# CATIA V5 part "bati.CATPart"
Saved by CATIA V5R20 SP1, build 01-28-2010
Part number: bati
Bounding box of the stored display mesh (mm): x -46.352 to 253.648, y 0 to 1170, z -91.16 to 708.84
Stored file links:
  C:\Users\Manon\Desktop\IAO\Pieces\bati.CATPart
  C:\Users\Manon\Desktop\IAO\assemblage\Assemblage_rlanglais.CATProduct
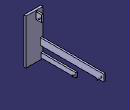
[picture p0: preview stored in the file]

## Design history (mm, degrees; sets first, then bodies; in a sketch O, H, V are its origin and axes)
External parameters (linked from other documents)
  External.ga = 1100 mm
Body1 (main body)
  Sketch1 on zx-plane, origin (0, 0, 0), H (-1, 0, 0), V (0, 0, 1)
    line L1 (-253.6482, 708.8397) -> (46.3518, 708.8397)
    line L2 (46.3518, 708.8397) -> (46.3518, -91.1603)
    line L3 (46.3518, -91.1603) -> (-253.6482, -91.1603)
    line L4 (-253.6482, -91.1603) -> (-253.6482, 708.8397)
    length L2 = 800
    length L3 = 300
    horizontal: L1 H, L3 H
    vertical: L2 V, L4 V
  Pad1: profile Sketch1, direction (0, 1, 0), length 40
  Sketch2 on end face of Pad1, origin (0, 40, 0), H (-1, 0, 0), V (0, 0, 1)
    line L1 (-76.0129, 690.5084) -> (-46.0129, 690.5084)
    line L2 (-46.0129, 690.5084) -> (-46.0129, 570.5084)
    line L3 (-46.0129, 570.5084) -> (-76.0129, 570.5084)
    line L4 (-76.0129, 570.5084) -> (-76.0129, 690.5084)
    length L2 = 120
    length L1 = 30
    horizontal: L1 H, L3 H
    vertical: L2 V, L4 V
  Pad2: profile Sketch2, direction (0, 1, 0), length 100
  Sketch3 on end face of Pad1, origin (0, 40, 0), H (-1, 0, 0), V (0, 0, 1)
    line L1 (13.9871, 14.155) -> (43.9871, 14.155)
    line L2 (43.9871, 14.155) -> (43.9871, -65.845)
    line L3 (43.9871, -65.845) -> (13.9871, -65.845)
    line L4 (13.9871, -65.845) -> (13.9871, 14.155)
    reference projected line E1 (-46.0129, 527.1475) -> (-46.0129, 647.1475) from edge [face of Pad2 from Sketch2.L2 | end face of Pad2]
    length L2 = 80
    length L3 = 30
    distance E1 L4 = 60
    horizontal: L1 H, L3 H
    vertical: L2 V, L4 V
  Pad3: profile Sketch3, direction (0, 1, 0), length 620
  Sketch4 on end face of Pad1, origin (0, 40, 0), H (-1, 0, 0), V (0, 0, 1)
    line L1 (3.9871, 249.8099) -> (33.9871, 249.8099)
    line L2 (33.9871, 249.8099) -> (33.9871, 129.8099)
    line L3 (33.9871, 129.8099) -> (3.9871, 129.8099)
    line L4 (3.9871, 129.8099) -> (3.9871, 249.8099)
    reference projected line E1 (-76.0129, 647.1475) -> (-76.0129, 527.1475) from edge [face of Pad2 from Sketch2.L4 | end face of Pad2]
    distance L2 L4 = 30
    length L2 = 120
    distance E1 L4 = 80
    horizontal: L1 H, L3 H
    vertical: L2 V, L4 V
  Pad4: profile Sketch4, direction (0, 1, 0), length 1130
  Sketch5 on face of Pad2 from Sketch2.L4, origin (76.0129, 0, 0), H (0, 1, 0), V (0, 0, 1)
    circle A1 centre (120, 630.5084) radius 10
    point P1 (120, 630.5084)
    reference projected line E1 (140, 647.1475) -> (140, 527.1475) from edge [face of Pad2 from Sketch2.L4 | end face of Pad2]
    reference projected line E2 (40, 570.5084) -> (140, 570.5084) from edge [face of Pad2 from Sketch2.L3 | face of Pad2 from Sketch2.L4]
    radius A1 = 10
    distance P1 E1 = 20
    distance P1 E2 = 60
  Pad5: profile Sketch5, direction (1, 0, 0), length 30
  Sketch6 on face of Pad4 from Sketch4.L4, origin (-3.9871, 0, 0), H (0, 1, 0), V (0, 0, 1)
    circle A1 centre (1126.5391, 186.7979) radius 10
    point P1 (1126.5391, 186.7979)
    reference projected circle E1 centre (120, 630.5084) radius 10 from edge [face of Pad5 from Sketch5.A1 | end face of Pad5]
    radius A1 = 10
    distance P1 E1 = 1110
  Pad6: profile Sketch6, direction (1, 0, 0), length 80
  Sketch7 on face of Pad3 from Sketch3.L4, origin (-13.9871, 0, 0), H (0, 1, 0), V (0, 0, 1)
    circle A1 centre (629.0866, -37.6464) radius 10
    point P1 (629.0866, -37.6464)
    reference projected circle E1 centre (120, 630.5084) radius 10 from edge [face of Pad5 from Sketch5.A1 | end face of Pad5]
    radius A1 = 10
    distance P1 E1 = 830
  Pad7: profile Sketch7, direction (1, 0, 0), length 30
